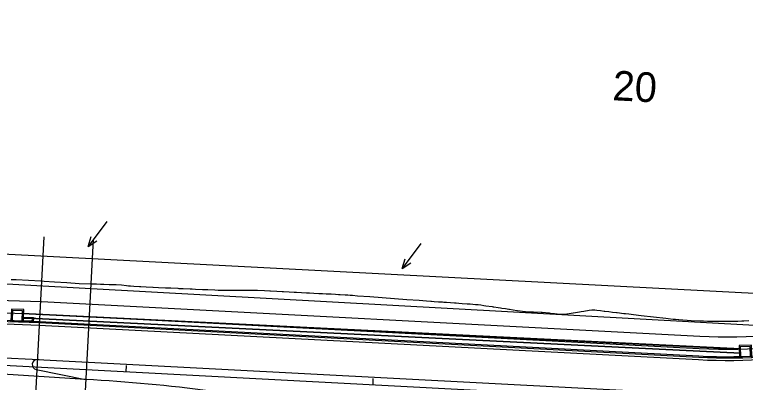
# Model space of a CAD drawing. Extents: x 670017 to 673226, y 705371 to 707498.
# Drawn here: x 671255.4 to 671551.1, y 706559.8 to 706708.6 of the extents above; entities that cross this region are included whole.
import ezdxf

# ---------------------------------------------------------------- set-up
doc = ezdxf.new("R2010")
doc.units = 0
for name, color, linetype in [('EL L 264', 7, 'Continuous'), ('R_Drainage Flow Lines', 7, 'Continuous'), ('R_Drainage Stage 1A', 7, 'Continuous'), ('R_Horz Alg', 7, 'Continuous'), ('R_Horz Alg Station', 7, 'Continuous'), ('R_Horz Alg Station Annot', 7, 'Continuous'), ('R_No Plot', 7, 'Continuous'), ('R_No Plot FOC', 7, 'Continuous'), ('R_Proposed Const Limits Stage 1A', 7, 'Continuous'), ('R_Proposed Median', 7, 'Continuous'), ('R_Proposed Road Stage 1A', 7, 'Continuous'), ('R_Proposed Sidewalk Stage 1A', 7, 'Continuous'), ('R_ROW', 7, 'Continuous'), ('R_Striping', 7, 'Continuous'), ('R_Water Annot', 7, 'Continuous'), ('S_EXIST_ROW', 7, 'Continuous')]:
    doc.layers.add(name, color=color, linetype=linetype)

# ---------------------------------------------------------------- blocks, each defined once
blk = doc.blocks.new('FLOW ARROW')
at = {"layer": 'R_Water Annot'}
for p, q in [((-12.57, 0), (0, 0)), ((0, 0), (-3.85, 1.4)), ((0, 0), (-3.85, -1.4))]:
    blk.add_line(p, q, dxfattribs=at)

msp = doc.modelspace()

# ---------------------------------------------------------------- linework, layer by layer
at = {"layer": 'EL L 264'}
for p, q in [((670890.23, 706596.66), (671265.36, 706582.98)), ((670890.23, 706596.66), (671265.36, 706582.98)), ((671265.36, 706582.98), (671532.16, 706568.98)), ((671265.36, 706582.98), (671532.16, 706568.98))]:
    msp.add_line(p, q, dxfattribs=at)
msp.add_arc((671543.74, 706789.68), 221, 266.9958, 296.5471, dxfattribs=at)
msp.add_arc((671543.74, 706789.68), 221, 266.9958, 296.5471, dxfattribs=at)
at = {"layer": 'R_Drainage Stage 1A'}
for p, q in [((671549.06, 706573.15), (671258.54, 706587.46)), ((671549.06, 706573.32), (671258.55, 706587.62)), ((671549.12, 706571.48), (671258.48, 706585.79)), ((671549.11, 706571.65), (671258.49, 706585.96))]:
    msp.add_line(p, q, dxfattribs=at)
for points in [[(671259.11, 706589.21), (671254.11, 706589.4), (671253.93, 706584.4), (671258.92, 706584.22)], [(671258.59, 706588.73), (671254.59, 706588.88), (671254.45, 706584.88), (671258.44, 706584.73)], [(671259, 706586.22), (671263, 706586.07), (671262.92, 706584.07), (671258.92, 706584.22)], [(671258.98, 706585.72), (671262.48, 706585.59), (671262.44, 706584.59), (671258.94, 706584.72)], [(671553.51, 706574.88), (671548.51, 706574.72), (671548.68, 706569.72), (671553.68, 706569.88)], [(671553.03, 706574.37), (671549.03, 706574.23), (671549.16, 706570.23), (671553.16, 706570.37)]]:
    msp.add_lwpolyline(points, close=True, dxfattribs=at)
at = {"layer": 'R_Horz Alg'}
msp.add_line((670501.52, 706606.05), (672734.79, 706488.84), dxfattribs=at)
at = {"layer": 'R_Horz Alg Station'}
for points in [[(671300.55, 706566.61), (671300.42, 706564.12)], [(671400.41, 706561.37), (671400.28, 706558.88)]]:
    msp.add_lwpolyline(points, dxfattribs=at)
at = {"layer": 'R_No Plot'}
for points in [[(671267.23, 706618.66), (671262.13, 706521.4)], [(671287.21, 706617.62), (671282.1, 706520.35)]]:
    msp.add_lwpolyline(points, dxfattribs=at)
at = {"layer": 'R_No Plot FOC'}
for p, q in [((670890.28, 706597.66), (671265.41, 706583.98)), ((671265.41, 706583.98), (671532.21, 706569.98))]:
    msp.add_line(p, q, dxfattribs=at)
msp.add_arc((671543.74, 706789.68), 220, 266.9958, 296.5471, dxfattribs=at)
at = {"layer": 'R_Proposed Const Limits Stage 1A'}
msp.add_lwpolyline([(671254.03, 706601.46), (671256.02, 706601.37), (671261.02, 706601.12), (671266.01, 706600.87), (671266.01, 706600.87), (671266.31, 706600.84), (671266.53, 706600.83), (671266.53, 706600.83), (671267.3, 706600.78), (671271.52, 706600.51), (671276.51, 706600.18), (671281.5, 706599.86), (671286.49, 706599.66), (671286.5, 706599.66), (671288.6, 706599.6), (671290.09, 706599.55), (671291.49, 706599.5), (671293.62, 706599.43), (671295.4, 706599.37), (671296.49, 706599.34), (671298.63, 706599.24), (671300.7, 706599), (671301.48, 706598.91), (671302.24, 706598.82), (671303.62, 706598.66), (671305.99, 706598.54), (671306.46, 706598.52), (671308.63, 706598.42), (671311.3, 706598.3), (671311.46, 706598.3), (671313.64, 706598.2), (671316.45, 706598.08), (671316.6, 706598.07), (671318.64, 706597.98), (671321.45, 706597.85), (671321.9, 706597.83), (671323.65, 706597.76), (671326.44, 706597.63), (671327.2, 706597.6), (671328.65, 706597.53), (671331.44, 706597.4), (671332.5, 706597.36), (671333.65, 706597.3), (671336.43, 706597.18), (671337.79, 706597.11), (671338.65, 706597.07), (671341.43, 706597.04), (671343.09, 706597.05), (671343.65, 706597.06), (671346.44, 706597.08), (671348.39, 706597.1), (671348.65, 706597.1), (671351.45, 706597.12), (671353.65, 706597.07), (671353.68, 706597.07), (671356.45, 706596.93), (671358.63, 706596.82), (671358.96, 706596.8), (671361.44, 706596.68), (671363.61, 706596.57), (671364.23, 706596.54), (671366.43, 706596.43), (671368.58, 706596.32), (671369.5, 706596.27), (671371.43, 706596.17), (671373.54, 706596.07), (671374.76, 706596), (671376.42, 706595.92), (671378.5, 706595.81), (671380.01, 706595.73), (671381.42, 706595.66), (671383.46, 706595.55), (671385.26, 706595.46), (671386.41, 706595.4), (671387.18, 706595.36), (671389.17, 706595.25), (671390.17, 706595.17), (671391.17, 706595.1), (671391.4, 706595.08), (671392.17, 706595.02), (671394.16, 706594.86), (671399.15, 706594.47), (671404.13, 706594.08), (671409.12, 706593.7), (671414.11, 706593.35), (671419.1, 706593), (671420.61, 706592.89), (671422.09, 706592.79), (671423.78, 706592.67), (671424.09, 706592.65), (671425.15, 706592.57), (671426.96, 706592.44), (671428.49, 706592.33), (671429.07, 706592.29), (671430.14, 706592.21), (671431.83, 706592.09), (671433.33, 706591.98), (671434.06, 706591.93), (671435.18, 706591.85), (671436.53, 706591.75), (671438.53, 706591.61), (671439.05, 706591.57), (671439.72, 706591.52), (671441.89, 706591.36), (671442.92, 706591.28), (671444.03, 706591.12), (671445.25, 706590.93), (671446.11, 706590.8), (671448.6, 706590.43), (671449, 706590.37), (671449.31, 706590.32), (671450.99, 706590.07), (671451.95, 706589.92), (671452.5, 706589.84), (671453.97, 706589.62), (671455.31, 706589.42), (671455.69, 706589.36), (671458.67, 706588.91), (671458.89, 706588.88), (671458.94, 706588.87), (671458.94, 706588.87), (671462.03, 706588.41), (671462.08, 706588.4), (671463.91, 706588.3), (671465.3, 706588.27), (671465.41, 706588.27), (671468.51, 706588.22), (671468.79, 706588.22), (671468.92, 706588.21), (671471.71, 706587.87), (671472.16, 706587.81), (671473.89, 706587.59), (671474.9, 706587.46), (671475.52, 706587.38), (671478.11, 706587.39), (671478.89, 706587.52), (671478.91, 706587.52), (671481.35, 706587.91), (671482.32, 706588.07), (671483.94, 706588.33), (671484.58, 706588.44), (671485.73, 706588.62), (671487.81, 706588.96), (671488.99, 706589.15), (671489.13, 706589.18), (671490.14, 706589.12), (671491.01, 706589.01), (671492.49, 706588.84), (671493.97, 706588.66), (671494.18, 706588.64), (671495.83, 706588.44), (671497.34, 706588.26), (671498.95, 706588.07), (671499.17, 706588.05), (671501.93, 706587.72), (671502.51, 706587.65), (671503.93, 706587.49), (671505.84, 706587.26), (671508.9, 706586.9), (671513.88, 706586.31), (671518.85, 706585.72), (671519.85, 706585.6), (671521.84, 706585.4), (671522.84, 706585.32), (671523.84, 706585.25), (671524.2, 706585.22), (671529.19, 706584.86), (671532.98, 706584.68), (671534.09, 706584.63), (671535.76, 706584.58), (671537.14, 706584.54), (671538.55, 706584.51), (671538.74, 706584.51), (671541.34, 706584.49), (671543.38, 706584.5), (671544.12, 706584.5), (671545.42, 706584.52), (671546.9, 706584.56), (671548.03, 706584.6), (671549.69, 706584.66), (671550.49, 706584.7), (671552.47, 706584.81)], dxfattribs=at)
at = {"layer": 'R_Proposed Median'}
for p, q in [((671264.63, 706569), (671555.33, 706553.74)), ((671264.12, 706565.04), (671284.09, 706560.97))]:
    msp.add_line(p, q, dxfattribs=at)
for centre, radius, start, end in [((671264.52, 706567), 2, 86.9958, 258.465), ((671247.37, 705886.97), 675, 78.24453, 86.88194)]:
    msp.add_arc(centre, radius, start, end, dxfattribs=at)
at = {"layer": 'R_Proposed Road Stage 1A'}
for p, q in [((670890.29, 706598.16), (671265.44, 706584.48)), ((670890.23, 706596.66), (671265.36, 706582.98)), ((671265.44, 706584.48), (671532.24, 706570.48)), ((671265.36, 706582.98), (671532.16, 706568.98))]:
    msp.add_line(p, q, dxfattribs=at)
for radius in [219.5, 221]:
    msp.add_arc((671543.74, 706789.68), radius, 266.9958, 296.5471, dxfattribs=at)
at = {"layer": 'R_Proposed Sidewalk Stage 1A'}
for p, q in [((670881.07, 706606.48), (671266.24, 706592.45)), ((670882.32, 706601.44), (671266.02, 706587.45)), ((670895.08, 706600.97), (671265.98, 706587.45)), ((671266.24, 706592.45), (671532.65, 706578.47)), ((671266.02, 706587.45), (671532.39, 706573.47))]:
    msp.add_line(p, q, dxfattribs=at)
for radius, end in [(211.5, 283.194), (216.5, 283.5818)]:
    msp.add_arc((671543.74, 706789.68), radius, 266.9958, end, dxfattribs=at)
at = {"layer": 'R_ROW'}
msp.add_lwpolyline([(670753.27, 706632.89), (670820.8, 706679.41), (670885.98, 706681), (670933.29, 706628.45), (671562.42, 706595.43), (671640.16, 706635.12), (671682.63, 706708.58)], dxfattribs=at)
at = {"layer": 'R_Striping'}
for p in [(671265.3, 706568.97), (671284.09, 706560.97)]:
    msp.add_line(p, (670881, 706586.13), dxfattribs=at)
at = {"layer": 'S_EXIST_ROW'}
msp.add_lwpolyline([(670020.59, 706668.53), (670619.99, 706639.58), (670619.86, 706634.58), (671728.16, 706573.3), (673225.88, 706490.48)], dxfattribs=at)

# ---------------------------------------------------------------- block references
at = {"layer": 'R_Drainage Flow Lines', "rotation": -126.70314512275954}
for p in [(671285.19, 706614.83), (671412.25, 706605.86)]:
    msp.add_blockref('FLOW ARROW', p, dxfattribs=at)

# ---------------------------------------------------------------- texts
at = {"layer": 'R_Horz Alg Station Annot'}
msp.add_text('20', height=12, rotation=356.9958, dxfattribs=at).set_placement((671497.14, 706673.96))

doc.saveas('drawing.dxf')
